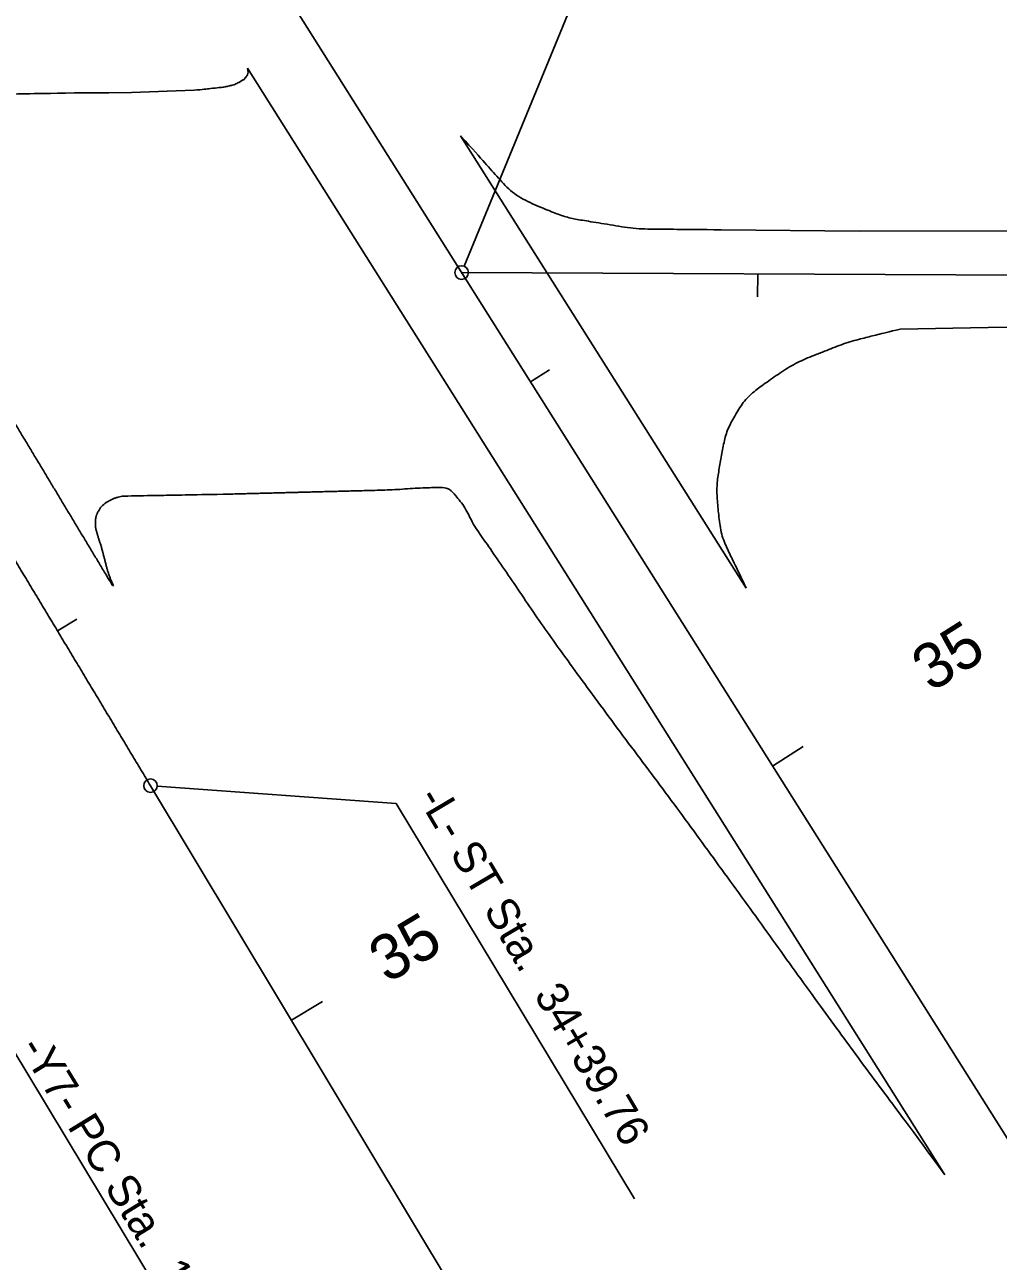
# Model space of a CAD drawing. Extents: x 1778969 to 1790720, y 807089 to 817794.
# Drawn here: x 1780431.5 to 1780645.9, y 815492.9 to 815765.2 of the extents above; entities that cross this region are included whole.
import ezdxf

# ---------------------------------------------------------------- set-up
doc = ezdxf.new("R2010")
doc.units = 0
for name, color, linetype in [('Prop Horizontal Alignment', 7, 'Continuous'), ('Prop Horizontal Alignment Station Label', 7, 'Continuous'), ('Prop Horizontal Alignment Tick Label', 7, 'Continuous'), ('Prop Horizontal Alignment Tick Large', 7, 'Continuous'), ('Prop Horizontal Alignment Tick Small', 7, 'Continuous'), ('Prop Rem of Exist Asph Pvmt', 7, 'Continuous')]:
    doc.layers.add(name, color=color, linetype=linetype)

msp = doc.modelspace()

# ---------------------------------------------------------------- linework, layer by layer
at = {"layer": 'Prop Horizontal Alignment'}
for p, q in [((1780487.95, 815773.73), (1781812.35, 813671.96)), ((1780487.95, 815773.73), (1781812.35, 813671.96)), ((1780992.95, 815708.33), (1780527.74, 815710.58)), ((1780459.21, 815597.59), (1781830.87, 813314.76)), ((1780459.21, 815597.59), (1781830.87, 813314.76))]:
    msp.add_line(p, q, dxfattribs=at)
msp.add_spline([(1780459.21, 815597.59), (1780457.12, 815601.06), (1780455.03, 815604.54), (1780452.95, 815608.01), (1780450.86, 815611.49), (1780448.77, 815614.96), (1780446.68, 815618.44), (1780444.59, 815621.91), (1780442.51, 815625.39), (1780440.42, 815628.86), (1780438.33, 815632.34), (1780436.24, 815635.81), (1780434.15, 815639.29), (1780432.06, 815642.76), (1780429.97, 815646.23), (1780427.88, 815649.71), (1780425.79, 815653.18), (1780423.7, 815656.66), (1780421.61, 815660.13), (1780419.52, 815663.6), (1780417.43, 815667.08), (1780415.34, 815670.55), (1780413.25, 815674.02), (1780411.15, 815677.49), (1780409.06, 815680.97), (1780406.97, 815684.44), (1780404.87, 815687.91), (1780402.78, 815691.38), (1780400.69, 815694.85), (1780398.59, 815698.32), (1780396.5, 815701.79), (1780394.4, 815705.26), (1780392.3, 815708.73), (1780390.21, 815712.2), (1780388.11, 815715.67), (1780386.01, 815719.14), (1780383.91, 815722.61), (1780381.81, 815726.08), (1780379.72, 815729.55), (1780377.61, 815733.02), (1780375.51, 815736.48), (1780373.41, 815739.95), (1780371.31, 815743.42), (1780369.21, 815746.88), (1780367.1, 815750.35), (1780365, 815753.81), (1780362.89, 815757.28), (1780360.79, 815760.74), (1780358.68, 815764.2), (1780356.57, 815767.67), (1780354.47, 815771.13), (1780352.36, 815774.59), (1780350.25, 815778.05), (1780348.14, 815781.52), (1780346.02, 815784.98), (1780343.91, 815788.44), (1780341.8, 815791.9), (1780339.68, 815795.35), (1780337.57, 815798.81), (1780335.45, 815802.27), (1780333.33, 815805.73), (1780331.22, 815809.18), (1780329.1, 815812.64), (1780326.98, 815816.1), (1780324.85, 815819.55), (1780322.73, 815823), (1780320.61, 815826.46), (1780318.48, 815829.91), (1780316.36, 815833.36), (1780314.23, 815836.81), (1780312.1, 815840.27), (1780309.97, 815843.72), (1780307.84, 815847.16), (1780305.71, 815850.61), (1780303.58, 815854.06)], degree=3, dxfattribs=at)
msp.add_spline([(1780459.21, 815597.59), (1780457.12, 815601.06), (1780455.03, 815604.54), (1780452.95, 815608.01), (1780450.86, 815611.49), (1780448.77, 815614.96), (1780446.68, 815618.44), (1780444.59, 815621.91), (1780442.51, 815625.39), (1780440.42, 815628.86), (1780438.33, 815632.34), (1780436.24, 815635.81), (1780434.15, 815639.29), (1780432.06, 815642.76), (1780429.97, 815646.23), (1780427.88, 815649.71), (1780425.79, 815653.18), (1780423.7, 815656.66), (1780421.61, 815660.13), (1780419.52, 815663.6), (1780417.43, 815667.08), (1780415.34, 815670.55), (1780413.25, 815674.02), (1780411.15, 815677.49), (1780409.06, 815680.97), (1780406.97, 815684.44), (1780404.87, 815687.91), (1780402.78, 815691.38), (1780400.69, 815694.85), (1780398.59, 815698.32), (1780396.5, 815701.79), (1780394.4, 815705.26), (1780392.3, 815708.73), (1780390.21, 815712.2), (1780388.11, 815715.67), (1780386.01, 815719.14), (1780383.91, 815722.61), (1780381.81, 815726.08), (1780379.72, 815729.55), (1780377.61, 815733.02), (1780375.51, 815736.48), (1780373.41, 815739.95), (1780371.31, 815743.42), (1780369.21, 815746.88), (1780367.1, 815750.35), (1780365, 815753.81), (1780362.89, 815757.28), (1780360.79, 815760.74), (1780358.68, 815764.2), (1780356.57, 815767.67), (1780354.47, 815771.13), (1780352.36, 815774.59), (1780350.25, 815778.05), (1780348.14, 815781.52), (1780346.02, 815784.98), (1780343.91, 815788.44), (1780341.8, 815791.9), (1780339.68, 815795.35), (1780337.57, 815798.81), (1780335.45, 815802.27), (1780333.33, 815805.73), (1780331.22, 815809.18), (1780329.1, 815812.64), (1780326.98, 815816.1), (1780324.85, 815819.55), (1780322.73, 815823), (1780320.61, 815826.46), (1780318.48, 815829.91), (1780316.36, 815833.36), (1780314.23, 815836.81), (1780312.1, 815840.27), (1780309.97, 815843.72), (1780307.84, 815847.16), (1780305.71, 815850.61), (1780303.58, 815854.06)], degree=3, dxfattribs=at)
at = {"layer": 'Prop Horizontal Alignment Station Label'}
for p, q in [((1780528.31, 815711.97), (1780572.79, 815820.24)), ((1780460.71, 815597.48), (1780513.3, 815593.65)), ((1780513.3, 815593.65), (1780565.84, 815506.62)), ((1780428.51, 815540.13), (1780485.01, 815446.53))]:
    msp.add_line(p, q, dxfattribs=at)
for centre in [(1780527.74, 815710.58), (1780459.21, 815597.59)]:
    msp.add_circle(centre, 1.5, dxfattribs=at)
at = {"layer": 'Prop Horizontal Alignment Tick Large'}
for p, q in [((1780596.21, 815601.92), (1780602.98, 815606.19)), ((1780490.24, 815545.95), (1780497.09, 815550.07))]:
    msp.add_line(p, q, dxfattribs=at)
at = {"layer": 'Prop Horizontal Alignment Tick Small'}
for p, q in [((1780592.96, 815710.26), (1780592.93, 815705.26)), ((1780542.9, 815686.53), (1780547.13, 815689.19)), ((1780438.73, 815631.67), (1780443.02, 815634.25))]:
    msp.add_line(p, q, dxfattribs=at)
at = {"layer": 'Prop Rem of Exist Asph Pvmt'}
for p, q in [((1780634.14, 815511.92), (1780480.6, 815755.57)), ((1780450.01, 815750.17), (1780442.45, 815750.14)), ((1780455.05, 815750.2), (1780450.01, 815750.17)), ((1780468.8, 815750.72), (1780455.05, 815750.2)), ((1780527.52, 815740.7), (1780590.44, 815641.06)), ((1780450.9, 815641.57), (1780451.09, 815641.7))]:
    msp.add_line(p, q, dxfattribs=at)
for points in [[(1780703.01, 815719.84), (1780700.12, 815719.83), (1780656.8, 815719.78), (1780615.39, 815719.68), (1780584.94, 815720.01)], [(1780624.33, 815698.15), (1780643.74, 815698.45), (1780682.2, 815699.14), (1780702.91, 815699.18)]]:
    msp.add_lwpolyline(points, dxfattribs=at)
for points, degree in [([(1780442.45, 815750.14), (1780436.84, 815750.04), (1780431.23, 815749.93), (1780425.62, 815749.83), (1780420.98, 815749.74), (1780416.34, 815749.45), (1780411.7, 815749.28), (1780408.79, 815749.18), (1780405.87, 815749.19), (1780402.96, 815749.69), (1780401.22, 815749.98), (1780399.64, 815751.19), (1780398.66, 815752.64), (1780388.94, 815767.06), (1780379.66, 815781.49), (1780370.43, 815796.1), (1780361.34, 815810.47), (1780352.62, 815825.06), (1780343.25, 815839.24), (1780334.48, 815852.51), (1780325.37, 815865.54), (1780316.27, 815878.58), (1780306.36, 815892.78), (1780296.43, 815906.96), (1780286.42, 815921.09), (1780276.7, 815934.8), (1780266.56, 815948.21), (1780256.84, 815961.93), (1780247.46, 815975.17), (1780238.26, 815988.54), (1780229.46, 816002.18), (1780222.11, 816013.58), (1780214.83, 816025.02), (1780207.48, 816036.42)], 3), ([(1780480.6, 815755.57), (1780480.78, 815754.83), (1780480.59, 815754.07), (1780480.02, 815753.36), (1780479.82, 815753.1), (1780479.6, 815753.01), (1780479.36, 815752.86), (1780479.14, 815752.72), (1780478.92, 815752.58), (1780478.69, 815752.46), (1780478.25, 815752.22), (1780477.8, 815752.01), (1780477.31, 815751.88), (1780476.36, 815751.61), (1780475.39, 815751.42), (1780474.42, 815751.32), (1780472.55, 815751.12), (1780470.68, 815750.92), (1780468.8, 815750.72)], 3), ([(1780384.2, 815752.11), (1780384.33, 815751.9), (1780384.46, 815751.68), (1780384.59, 815751.47), (1780385.29, 815750.31), (1780385.99, 815749.16), (1780386.69, 815748), (1780387.39, 815746.84), (1780388.09, 815745.69), (1780388.79, 815744.53), (1780389.49, 815743.37), (1780390.2, 815742.22), (1780390.9, 815741.06), (1780391.6, 815739.9), (1780392.3, 815738.75), (1780393, 815737.59), (1780393.7, 815736.43), (1780394.4, 815735.28), (1780395.1, 815734.12), (1780395.8, 815732.96), (1780396.5, 815731.81), (1780397.2, 815730.65), (1780397.9, 815729.49), (1780398.6, 815728.34), (1780399.3, 815727.18), (1780400, 815726.02), (1780400.7, 815724.87), (1780401.4, 815723.71), (1780402.1, 815722.55), (1780402.8, 815721.39), (1780403.5, 815720.24), (1780404.2, 815719.08), (1780404.9, 815717.92), (1780405.6, 815716.76), (1780406.29, 815715.61), (1780406.99, 815714.45), (1780407.69, 815713.29), (1780408.39, 815712.14), (1780409.09, 815710.98), (1780409.79, 815709.82), (1780410.49, 815708.66), (1780411.19, 815707.51), (1780411.89, 815706.35), (1780412.58, 815705.19), (1780413.28, 815704.03), (1780413.98, 815702.88), (1780414.68, 815701.72), (1780415.38, 815700.56), (1780416.08, 815699.4), (1780416.78, 815698.24), (1780417.47, 815697.09), (1780418.17, 815695.93), (1780418.87, 815694.77), (1780419.57, 815693.61), (1780420.27, 815692.46), (1780420.96, 815691.3), (1780421.66, 815690.14), (1780422.36, 815688.98), (1780423.06, 815687.82), (1780423.76, 815686.67), (1780424.45, 815685.51), (1780425.15, 815684.35), (1780425.85, 815683.19), (1780426.55, 815682.03), (1780427.24, 815680.88), (1780427.94, 815679.72), (1780428.64, 815678.56), (1780429.34, 815677.4), (1780430.03, 815676.24), (1780430.73, 815675.09), (1780431.43, 815673.93), (1780432.13, 815672.77), (1780432.82, 815671.61), (1780433.52, 815670.45), (1780434.22, 815669.3), (1780434.92, 815668.14), (1780435.61, 815666.98), (1780436.31, 815665.82), (1780437.01, 815664.66), (1780437.7, 815663.5), (1780438.4, 815662.35), (1780439.1, 815661.19), (1780439.79, 815660.03), (1780440.49, 815658.87), (1780441.19, 815657.71), (1780441.88, 815656.55), (1780442.58, 815655.4), (1780443.28, 815654.24), (1780443.97, 815653.08), (1780444.67, 815651.92), (1780445.37, 815650.76), (1780446.06, 815649.61), (1780446.76, 815648.45), (1780447.46, 815647.29), (1780448.15, 815646.13), (1780448.85, 815644.97), (1780449.55, 815643.81), (1780450, 815643.07), (1780450.45, 815642.32), (1780450.9, 815641.57)], 3), ([(1780584.94, 815720.01), (1780580.2, 815720.05), (1780575.46, 815720.1), (1780570.71, 815720.14), (1780565.55, 815720.19), (1780560.45, 815721.12), (1780555.33, 815721.93), (1780552.47, 815722.38), (1780549.72, 815723.11), (1780546.99, 815724.21), (1780542.79, 815725.9), (1780538.78, 815728.12), (1780535.83, 815731.42), (1780533.06, 815734.51), (1780530.29, 815737.61), (1780527.52, 815740.7)], 3), ([(1780590.44, 815641.06), (1780589.16, 815643.73), (1780587.88, 815646.4), (1780586.6, 815649.08), (1780584.99, 815652.44), (1780584.43, 815656.3), (1780584.12, 815659.98), (1780583.87, 815663.13), (1780584.27, 815666.34), (1780584.84, 815669.5), (1780585.42, 815672.8), (1780586.18, 815675.94), (1780587.9, 815678.98), (1780589.68, 815682.1), (1780592.07, 815684.39), (1780594.93, 815686.41), (1780598.29, 815688.78), (1780601.62, 815690.85), (1780605.36, 815692.33), (1780609.08, 815693.8), (1780612.77, 815695.25), (1780616.62, 815696.22), (1780619.19, 815696.86), (1780621.76, 815697.5), (1780624.33, 815698.15)], 3), ([(1780475.21, 815661.76), (1780485.71, 815662.03), (1780496.2, 815662.3), (1780506.7, 815662.57)], 2), ([(1780506.7, 815662.57), (1780507.3, 815662.58), (1780507.91, 815662.6), (1780508.51, 815662.62), (1780513.01, 815662.73), (1780517.51, 815663.11), (1780522.01, 815663.25), (1780523.51, 815663.3), (1780525.22, 815662.92), (1780526.24, 815661.69), (1780528.65, 815658.78), (1780529.97, 815655.62), (1780532, 815652.69), (1780538.9, 815642.74), (1780545.62, 815632.66), (1780552.77, 815622.87), (1780562.62, 815609.38), (1780572.71, 815596.07), (1780582.54, 815582.57), (1780592.54, 815568.84), (1780602.41, 815555.01), (1780612.44, 815541.29), (1780619.63, 815531.47), (1780626.99, 815521.78), (1780634.14, 815511.92)], 3), ([(1780451.09, 815641.7), (1780450.76, 815642.29), (1780450.48, 815642.91), (1780450.24, 815643.55), (1780449.98, 815644.23), (1780449.76, 815644.92), (1780449.58, 815645.62), (1780449.39, 815646.32), (1780449.22, 815647.03), (1780449.03, 815647.73), (1780448.85, 815648.43), (1780448.67, 815649.13), (1780448.48, 815649.83), (1780448.31, 815650.49), (1780448.06, 815651.13), (1780447.86, 815651.78), (1780447.65, 815652.44), (1780447.46, 815653.09), (1780447.28, 815653.78), (1780447.11, 815654.44), (1780447.06, 815655.11), (1780447.08, 815655.77), (1780447.09, 815656.1), (1780447.13, 815656.43), (1780447.21, 815656.75), (1780447.25, 815656.92), (1780447.3, 815657.08), (1780447.35, 815657.24), (1780447.41, 815657.4), (1780447.47, 815657.56), (1780447.55, 815657.71), (1780448.18, 815658.85), (1780449.12, 815659.75), (1780450.24, 815660.4), (1780450.54, 815660.57), (1780450.83, 815660.7), (1780451.15, 815660.81), (1780451.45, 815660.92), (1780451.74, 815661.04), (1780452.06, 815661.11), (1780452.67, 815661.26), (1780453.3, 815661.36), (1780453.92, 815661.37), (1780461.02, 815661.5), (1780468.12, 815661.63), (1780475.21, 815661.76)], 3)]:
    msp.add_open_spline(points, degree=degree, dxfattribs=at)

# ---------------------------------------------------------------- texts
at = {"layer": 'Prop Horizontal Alignment Station Label'}
for s, rotation, p in [('-L- ST Sta.  34+39.76', 300.6018, (1780517.88, 815594.92)), ('-Y7- PC Sta.  14+36.28', 301.546, (1780430.17, 815539.87))]:
    msp.add_text(s, height=7, rotation=rotation, dxfattribs=at).set_placement(p)
at = {"layer": 'Prop Horizontal Alignment Tick Label'}
for rotation, p in [(32.2167, (1780631.16, 815618.04)), (31, (1780511.38, 815553.91))]:
    msp.add_text('35', height=10, rotation=rotation, dxfattribs=at).set_placement(p)

doc.saveas('drawing.dxf')
